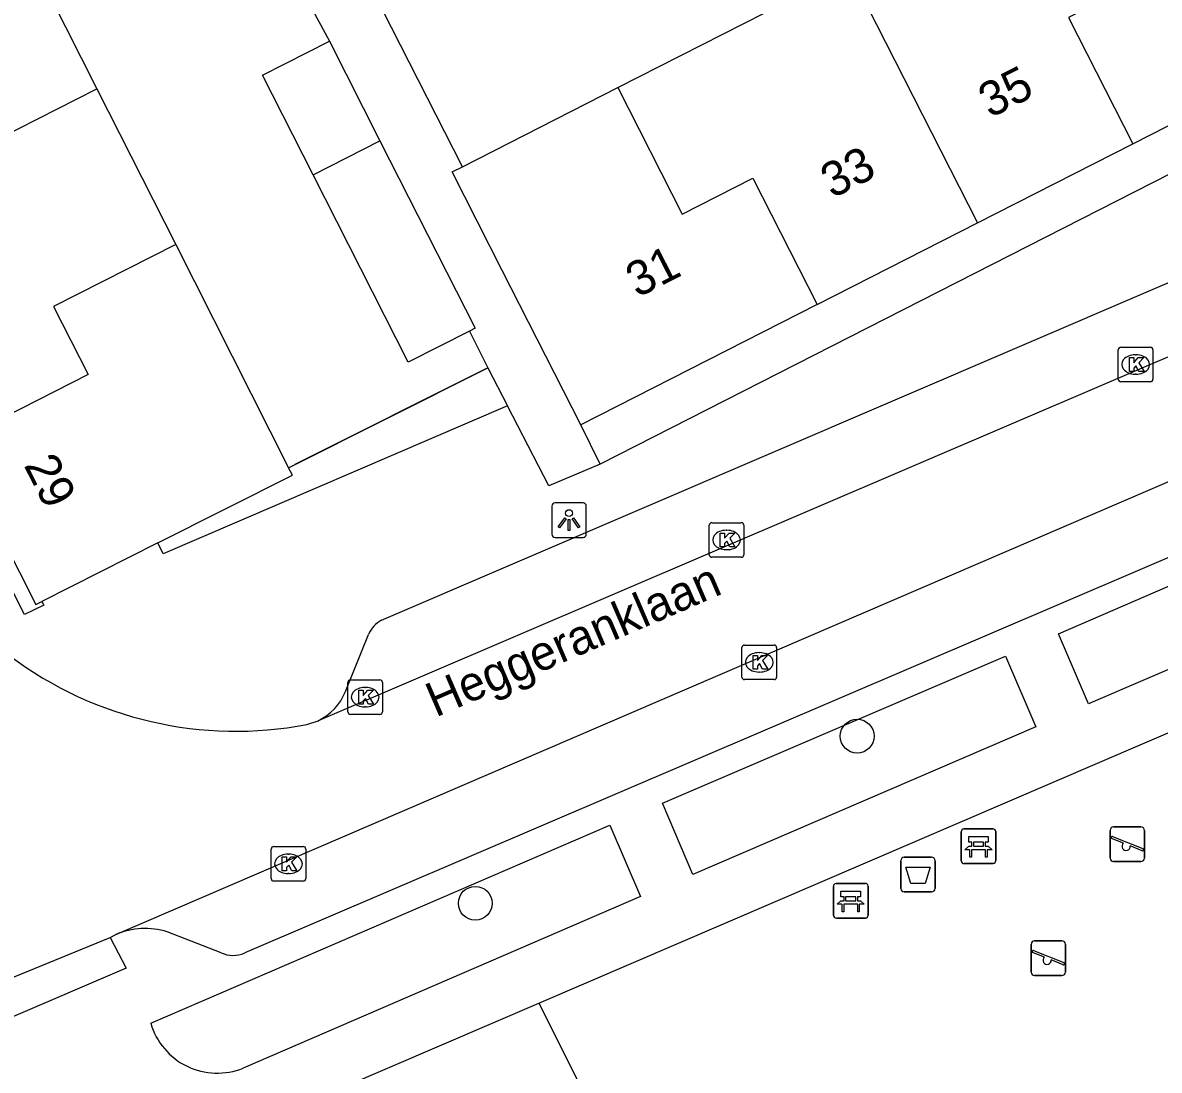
# Model space of a CAD drawing. Extents: x 162347 to 162868, y 381221 to 381813.
# Drawn here: x 162493.3 to 162526.14, y 381520.05 to 381550.31 of the extents above; entities that cross this region are included whole.
import ezdxf

# ---------------------------------------------------------------- set-up
doc = ezdxf.new("R2010")
doc.units = 0
for name, color, linetype in [('IMGEO_Afvalbak', 7, 'Continuous'), ('IMGEO_Bank', 7, 'Continuous'), ('IMGEO_Boom', 7, 'Continuous'), ('IMGEO_Groenvoorziening', 7, 'Continuous'), ('IMGEO_Kolk', 7, 'Continuous'), ('IMGEO_Lichtpunt', 7, 'Continuous'), ('IMGEO_Muur', 7, 'Continuous'), ('IMGEO_Openbare_ruimte_label', 7, 'Continuous'), ('IMGEO_Pand', 7, 'Continuous'), ('IMGEO_Pand_nummerreeks', 7, 'Continuous'), ('IMGEO_Rijbaan_lokaal_open', 7, 'Continuous'), ('IMGEO_Speelvoorziening', 7, 'Continuous'), ('IMGEO_Terreindeel_onvherhard', 7, 'Continuous'), ('IMGEO_Voetpad_open', 7, 'Continuous')]:
    doc.layers.add(name, color=color, linetype=linetype)

msp = doc.modelspace()

# ---------------------------------------------------------------- linework, layer by layer
at = {"layer": 'IMGEO_Afvalbak'}
for p, q in [((162518.676, 381525.301), (162518.676, 381526.101)), ((162518.676, 381526.101), (162518.676, 381525.301)), ((162518.776, 381526.201), (162519.566, 381526.201)), ((162519.566, 381526.201), (162518.776, 381526.201)), ((162519.666, 381526.101), (162519.666, 381525.301)), ((162519.666, 381525.301), (162519.666, 381526.101)), ((162519.566, 381525.201), (162518.776, 381525.201)), ((162518.776, 381525.201), (162519.566, 381525.201))]:
    msp.add_line(p, q, dxfattribs=at)
msp.add_lwpolyline([(162518.819, 381525.915), (162519.523, 381525.915), (162519.374, 381525.445), (162518.968, 381525.445), (162518.819, 381525.915)], dxfattribs=at)
for centre, start, end in [((162518.776, 381526.101), 90, 180), ((162518.776, 381526.101), 90, 180), ((162519.566, 381526.101), 0, 90), ((162519.566, 381526.101), 360, 90), ((162518.776, 381525.301), 180, 270), ((162518.776, 381525.301), 180, 270), ((162519.566, 381525.301), 270, 0), ((162519.566, 381525.301), 270, 0)]:
    msp.add_arc(centre, 0.1, start, end, dxfattribs=at)
at = {"layer": 'IMGEO_Bank'}
for p, q in [((162520.42, 381526.095), (162520.42, 381526.936)), ((162520.42, 381526.936), (162520.42, 381526.095)), ((162520.495, 381527.02), (162521.336, 381527.02)), ((162521.336, 381527.02), (162520.495, 381527.02)), ((162521.42, 381526.945), (162521.42, 381526.104)), ((162521.42, 381526.104), (162521.42, 381526.945)), ((162520.729, 381526.526), (162520.729, 381526.632)), ((162520.773, 381526.632), (162520.773, 381526.526)), ((162521.061, 381526.638), (162520.779, 381526.638)), ((162521.067, 381526.526), (162521.067, 381526.632)), ((162521.111, 381526.632), (162521.111, 381526.526)), ((162521.117, 381526.418), (162520.724, 381526.418)), ((162520.779, 381526.52), (162521.061, 381526.52)), ((162521.345, 381526.02), (162520.504, 381526.02)), ((162520.504, 381526.02), (162521.345, 381526.02)), ((162516.728, 381524.518), (162516.728, 381525.359)), ((162516.728, 381525.359), (162516.728, 381524.518)), ((162516.803, 381525.443), (162517.644, 381525.443)), ((162517.644, 381525.443), (162516.803, 381525.443)), ((162517.728, 381525.368), (162517.728, 381524.527)), ((162517.728, 381524.527), (162517.728, 381525.368)), ((162517.037, 381524.949), (162517.037, 381525.055)), ((162517.081, 381525.055), (162517.081, 381524.949)), ((162517.369, 381525.061), (162517.087, 381525.061)), ((162517.087, 381524.943), (162517.369, 381524.943)), ((162517.375, 381524.949), (162517.375, 381525.055)), ((162517.419, 381525.055), (162517.419, 381524.949)), ((162517.425, 381524.841), (162517.032, 381524.841)), ((162517.653, 381524.443), (162516.812, 381524.443)), ((162516.812, 381524.443), (162517.653, 381524.443))]:
    msp.add_line(p, q, dxfattribs=at)
for points in [[(162520.723, 381526.638), (162520.637, 381526.638), (162520.637, 381526.799), (162521.2, 381526.799), (162521.2, 381526.638), (162521.117, 381526.638)], [(162520.667, 381526.418), (162520.525, 381526.418), (162520.637, 381526.52), (162520.723, 381526.52)], [(162520.717, 381526.411), (162520.717, 381526.204), (162520.674, 381526.204), (162520.674, 381526.411)], [(162521.117, 381526.52), (162521.2, 381526.52), (162521.312, 381526.418), (162521.173, 381526.418)], [(162521.167, 381526.411), (162521.167, 381526.204), (162521.123, 381526.204), (162521.123, 381526.411)], [(162516.975, 381524.841), (162516.833, 381524.841), (162516.945, 381524.943), (162517.031, 381524.943)], [(162517.031, 381525.061), (162516.945, 381525.061), (162516.945, 381525.222), (162517.508, 381525.222), (162517.508, 381525.061), (162517.425, 381525.061)], [(162517.425, 381524.943), (162517.508, 381524.943), (162517.62, 381524.841), (162517.481, 381524.841)], [(162517.025, 381524.834), (162517.025, 381524.627), (162516.982, 381524.627), (162516.982, 381524.834)], [(162517.475, 381524.834), (162517.475, 381524.627), (162517.431, 381524.627), (162517.431, 381524.834)]]:
    msp.add_lwpolyline(points, dxfattribs=at)
for centre, radius, start, end in [((162520.498, 381526.942), 0.0779, 92.4484, 184.2845), ((162520.498, 381526.942), 0.0779, 92.4484, 184.2845), ((162521.342, 381526.942), 0.0779, 2.4484, 94.2845), ((162521.342, 381526.942), 0.0779, 2.4484, 94.2845), ((162520.722, 381526.631), 0.00671, 2.8957, 87.1043), ((162520.779, 381526.631), 0.00671, 92.8957, 177.1043), ((162521.061, 381526.631), 0.00671, 2.8957, 87.1043), ((162521.118, 381526.631), 0.00671, 92.8957, 177.1043), ((162520.667, 381526.411), 0.00671, 2.8957, 87.1043), ((162520.724, 381526.411), 0.00671, 92.8957, 177.1043), ((162520.722, 381526.527), 0.00671, 272.8957, 357.1043), ((162520.779, 381526.527), 0.00671, 182.8957, 267.1043), ((162521.061, 381526.527), 0.00671, 272.8957, 357.1043), ((162521.118, 381526.527), 0.00671, 182.8957, 267.1043), ((162521.116, 381526.411), 0.00671, 2.8957, 87.1043), ((162521.173, 381526.411), 0.00671, 92.8957, 177.1043), ((162520.498, 381526.098), 0.0779, 182.4484, 274.2845), ((162520.498, 381526.098), 0.0779, 182.4484, 274.2845), ((162521.342, 381526.098), 0.0779, 272.4484, 4.2845), ((162521.342, 381526.098), 0.0779, 272.4484, 4.2845), ((162516.806, 381525.365), 0.0779, 92.4484, 184.2845), ((162516.806, 381525.365), 0.0779, 92.4484, 184.2845), ((162517.65, 381525.365), 0.0779, 2.4484, 94.2845), ((162517.65, 381525.365), 0.0779, 2.4484, 94.2845), ((162517.03, 381525.054), 0.00671, 2.8957, 87.1043), ((162517.03, 381524.95), 0.00671, 272.8957, 357.1043), ((162517.087, 381525.054), 0.00671, 92.8957, 177.1043), ((162517.087, 381524.95), 0.00671, 182.8957, 267.1043), ((162517.369, 381525.054), 0.00671, 2.8957, 87.1043), ((162517.369, 381524.95), 0.00671, 272.8957, 357.1043), ((162517.426, 381525.054), 0.00671, 92.8957, 177.1043), ((162517.426, 381524.95), 0.00671, 182.8957, 267.1043), ((162516.975, 381524.834), 0.00671, 2.8957, 87.1043), ((162517.032, 381524.834), 0.00671, 92.8957, 177.1043), ((162517.424, 381524.834), 0.00671, 2.8957, 87.1043), ((162517.481, 381524.834), 0.00671, 92.8957, 177.1043), ((162516.806, 381524.521), 0.0779, 182.4484, 274.2845), ((162516.806, 381524.521), 0.0779, 182.4484, 274.2845), ((162517.65, 381524.521), 0.0779, 272.4484, 4.2845), ((162517.65, 381524.521), 0.0779, 272.4484, 4.2845)]:
    msp.add_arc(centre, radius, start, end, dxfattribs=at)
at = {"layer": 'IMGEO_Boom'}
for centre in [(162517.413, 381529.699), (162506.378, 381524.87)]:
    msp.add_circle(centre, 0.489, dxfattribs=at)
at = {"layer": 'IMGEO_Groenvoorziening'}
msp.add_lwpolyline([(162508.217, 381521.986), (162509, 381520.416), (162514.4, 381509.584)], dxfattribs=at)
at = {"layer": 'IMGEO_Kolk'}
for p, q in [((162524.96, 381540.012), (162524.96, 381540.864)), ((162525.035, 381540.938), (162525.887, 381540.938)), ((162525.448, 381540.718), (162525.473, 381540.718)), ((162525.961, 381540.864), (162525.961, 381540.012)), ((162525.471, 381540.158), (162525.446, 381540.158)), ((162525.887, 381539.938), (162525.035, 381539.938)), ((162513.138, 381534.941), (162513.138, 381535.793)), ((162513.213, 381535.867), (162514.065, 381535.867)), ((162514.139, 381535.793), (162514.139, 381534.941)), ((162513.626, 381535.647), (162513.651, 381535.647)), ((162514.065, 381534.867), (162513.213, 381534.867)), ((162513.649, 381535.087), (162513.624, 381535.087)), ((162514.085, 381531.406), (162514.085, 381532.258)), ((162514.16, 381532.332), (162515.012, 381532.332)), ((162515.086, 381532.258), (162515.086, 381531.406)), ((162514.573, 381532.112), (162514.598, 381532.112)), ((162514.596, 381531.552), (162514.571, 381531.552)), ((162502.695, 381530.401), (162502.695, 381531.253)), ((162502.77, 381531.327), (162503.622, 381531.327)), ((162503.696, 381531.253), (162503.696, 381530.401)), ((162515.012, 381531.332), (162514.16, 381531.332)), ((162503.183, 381531.107), (162503.208, 381531.107)), ((162503.206, 381530.547), (162503.181, 381530.547)), ((162503.622, 381530.327), (162502.77, 381530.327)), ((162500.479, 381525.583), (162500.479, 381526.435)), ((162500.554, 381526.509), (162501.406, 381526.509)), ((162500.967, 381526.289), (162500.992, 381526.289)), ((162501.48, 381526.435), (162501.48, 381525.583)), ((162500.99, 381525.729), (162500.965, 381525.729)), ((162501.406, 381525.509), (162500.554, 381525.509))]:
    msp.add_line(p, q, dxfattribs=at)
for points in [[(162524.96, 381540.012), (162524.96, 381540.864)], [(162525.035, 381540.938), (162525.887, 381540.938)], [(162525.961, 381540.864), (162525.961, 381540.012)], [(162525.281, 381540.638), (162525.404, 381540.638), (162525.404, 381540.487), (162525.534, 381540.638), (162525.698, 381540.638), (162525.552, 381540.487), (162525.705, 381540.238), (162525.553, 381540.238), (162525.468, 381540.402), (162525.404, 381540.335), (162525.404, 381540.238), (162525.281, 381540.238), (162525.281, 381540.638)], [(162525.887, 381539.938), (162525.035, 381539.938)], [(162513.138, 381534.941), (162513.138, 381535.793)], [(162513.213, 381535.867), (162514.065, 381535.867)], [(162514.139, 381535.793), (162514.139, 381534.941)], [(162513.459, 381535.567), (162513.582, 381535.567), (162513.582, 381535.416), (162513.712, 381535.567), (162513.876, 381535.567), (162513.73, 381535.416), (162513.883, 381535.167), (162513.731, 381535.167), (162513.646, 381535.331), (162513.582, 381535.264), (162513.582, 381535.167), (162513.459, 381535.167), (162513.459, 381535.567)], [(162514.065, 381534.867), (162513.213, 381534.867)], [(162514.085, 381531.406), (162514.085, 381532.258)], [(162514.16, 381532.332), (162515.012, 381532.332)], [(162515.086, 381532.258), (162515.086, 381531.406)], [(162514.406, 381532.032), (162514.529, 381532.032), (162514.529, 381531.881), (162514.659, 381532.032), (162514.823, 381532.032), (162514.677, 381531.881), (162514.83, 381531.632), (162514.678, 381531.632), (162514.593, 381531.796), (162514.529, 381531.729), (162514.529, 381531.632), (162514.406, 381531.632), (162514.406, 381532.032)], [(162502.695, 381530.401), (162502.695, 381531.253)], [(162502.77, 381531.327), (162503.622, 381531.327)], [(162503.696, 381531.253), (162503.696, 381530.401)], [(162515.012, 381531.332), (162514.16, 381531.332)], [(162503.016, 381531.027), (162503.139, 381531.027), (162503.139, 381530.876), (162503.269, 381531.027), (162503.433, 381531.027), (162503.287, 381530.876), (162503.44, 381530.627), (162503.288, 381530.627), (162503.203, 381530.791), (162503.139, 381530.724), (162503.139, 381530.627), (162503.016, 381530.627), (162503.016, 381531.027)], [(162503.622, 381530.327), (162502.77, 381530.327)], [(162500.479, 381525.583), (162500.479, 381526.435)], [(162500.554, 381526.509), (162501.406, 381526.509)], [(162501.48, 381526.435), (162501.48, 381525.583)], [(162500.8, 381526.209), (162500.923, 381526.209), (162500.923, 381526.058), (162501.053, 381526.209), (162501.217, 381526.209), (162501.071, 381526.058), (162501.224, 381525.809), (162501.072, 381525.809), (162500.987, 381525.973), (162500.923, 381525.906), (162500.923, 381525.809), (162500.8, 381525.809), (162500.8, 381526.209)], [(162501.406, 381525.509), (162500.554, 381525.509)]]:
    msp.add_lwpolyline(points, dxfattribs=at)
for centre, start, end in [((162525.037, 381540.862), 91.552, 178.448), ((162525.037, 381540.862), 91.552, 178.448), ((162525.885, 381540.862), 1.552, 88.448), ((162525.885, 381540.862), 1.552, 88.448), ((162525.037, 381540.014), 181.552, 268.448), ((162525.037, 381540.014), 181.552, 268.448), ((162525.885, 381540.014), 271.552, 358.448), ((162525.885, 381540.014), 271.552, 358.448), ((162513.215, 381535.791), 91.552, 178.448), ((162513.215, 381535.791), 91.552, 178.448), ((162514.063, 381535.791), 1.552, 88.448), ((162514.063, 381535.791), 1.552, 88.448), ((162513.215, 381534.943), 181.552, 268.448), ((162513.215, 381534.943), 181.552, 268.448), ((162514.063, 381534.943), 271.552, 358.448), ((162514.063, 381534.943), 271.552, 358.448), ((162514.162, 381532.256), 91.552, 178.448), ((162514.162, 381532.256), 91.552, 178.448), ((162515.01, 381532.256), 1.552, 88.448), ((162515.01, 381532.256), 1.552, 88.448), ((162502.772, 381531.251), 91.552, 178.448), ((162502.772, 381531.251), 91.552, 178.448), ((162503.62, 381531.251), 1.552, 88.448), ((162503.62, 381531.251), 1.552, 88.448), ((162514.162, 381531.408), 181.552, 268.448), ((162514.162, 381531.408), 181.552, 268.448), ((162515.01, 381531.408), 271.552, 358.448), ((162515.01, 381531.408), 271.552, 358.448), ((162502.772, 381530.403), 181.552, 268.448), ((162502.772, 381530.403), 181.552, 268.448), ((162503.62, 381530.403), 271.552, 358.448), ((162503.62, 381530.403), 271.552, 358.448), ((162500.556, 381526.433), 91.552, 178.448), ((162500.556, 381526.433), 91.552, 178.448), ((162501.404, 381526.433), 1.552, 88.448), ((162501.404, 381526.433), 1.552, 88.448), ((162500.556, 381525.585), 181.552, 268.448), ((162500.556, 381525.585), 181.552, 268.448), ((162501.404, 381525.585), 271.552, 358.448), ((162501.404, 381525.585), 271.552, 358.448)]:
    msp.add_arc(centre, 0.0765, start, end, dxfattribs=at)
for centre, major_axis, ratio, start_param, end_param in [((162525.447, 381540.438), (-0.387, 0.002), 0.722429, 4.712389, 7.853982), ((162525.472, 381540.438), (-0.39, 0.002), 0.717154, 1.570796, 4.712389), ((162513.625, 381535.367), (-0.387, 0.002), 0.722429, 4.712389, 7.853982), ((162513.65, 381535.367), (-0.39, 0.002), 0.717154, 1.570796, 4.712389), ((162514.572, 381531.832), (-0.387, 0.002), 0.722429, 4.712389, 7.853982), ((162514.597, 381531.832), (-0.39, 0.002), 0.717154, 1.570796, 4.712389), ((162503.182, 381530.827), (-0.387, 0.002), 0.722429, 4.712389, 7.853982), ((162503.207, 381530.827), (-0.39, 0.002), 0.717154, 1.570796, 4.712389), ((162500.966, 381526.009), (-0.387, 0.002), 0.722429, 4.712389, 7.853982), ((162500.991, 381526.009), (-0.39, 0.002), 0.717154, 1.570796, 4.712389)]:
    msp.add_ellipse(centre, major_axis=major_axis, ratio=ratio, start_param=start_param, end_param=end_param, dxfattribs=at)
at = {"layer": 'IMGEO_Lichtpunt'}
for p, q in [((162509.491, 381536.439), (162508.683, 381536.439)), ((162509.491, 381536.439), (162508.683, 381536.439)), ((162508.589, 381536.344), (162508.589, 381535.537)), ((162508.589, 381536.344), (162508.589, 381535.537)), ((162509.585, 381535.537), (162509.585, 381536.344)), ((162509.585, 381535.537), (162509.585, 381536.344)), ((162508.683, 381535.443), (162509.491, 381535.443)), ((162508.683, 381535.443), (162509.491, 381535.443))]:
    msp.add_line(p, q, dxfattribs=at)
for points in [[(162508.963, 381536.008), (162509.002, 381535.98), (162508.814, 381535.718), (162508.776, 381535.745), (162508.963, 381536.008)], [(162509.065, 381535.96), (162509.112, 381535.96), (162509.112, 381535.638), (162509.065, 381535.638), (162509.065, 381535.96)], [(162509.175, 381535.98), (162509.213, 381536.007), (162509.4, 381535.745), (162509.361, 381535.717), (162509.175, 381535.98)]]:
    msp.add_lwpolyline(points, dxfattribs=at)
msp.add_circle((162509.088, 381536.142), 0.0994, dxfattribs=at)
for centre, start, end in [((162508.683, 381536.344), 90, 180), ((162508.683, 381536.344), 90, 180), ((162509.491, 381536.344), 0, 90), ((162509.491, 381536.344), 0, 90), ((162508.683, 381535.537), 180, 270), ((162508.683, 381535.537), 180, 270), ((162509.491, 381535.537), 270, 0), ((162509.491, 381535.537), 270, 360)]:
    msp.add_arc(centre, 0.0946, start, end, dxfattribs=at)
at = {"layer": 'IMGEO_Muur'}
msp.add_lwpolyline([(162506.739, 381540.345), (162501.168, 381537.547)], dxfattribs=at)
at = {"layer": 'IMGEO_Pand'}
for points in [[(162523.625, 381555.117), (162525.484, 381551.465), (162523.52, 381550.466), (162525.378, 381546.813)], [(162493.17, 381552.905), (162495.445, 381548.407)], [(162510.497, 381548.437), (162517.175, 381551.836)], [(162517.175, 381551.836), (162520.892, 381544.53)], [(162525.378, 381546.813), (162532.073, 381550.22)], [(162501.689, 381545.918), (162500.228, 381548.796), (162502.162, 381549.778)], [(162502.162, 381549.778), (162503.623, 381546.9)], [(162488.041, 381544.647), (162495.445, 381548.407)], [(162495.445, 381548.407), (162497.722, 381543.904)], [(162506.006, 381546.152), (162510.497, 381548.437)], [(162510.497, 381548.437), (162512.355, 381544.785), (162514.399, 381545.825), (162516.259, 381542.172)], [(162501.689, 381545.918), (162503.623, 381546.9)], [(162503.623, 381546.9), (162506.372, 381541.485), (162506.208, 381541.402)], [(162520.892, 381544.53), (162525.378, 381546.813)], [(162509.427, 381538.695), (162507.159, 381543.152), (162505.709, 381546.001), (162506.006, 381546.152)], [(162506.208, 381541.402), (162504.438, 381540.503), (162501.689, 381545.918)], [(162516.259, 381542.172), (162520.892, 381544.53)], [(162497.722, 381543.904), (162494.191, 381542.111), (162495.188, 381540.147), (162491.312, 381538.178)], [(162497.722, 381543.904), (162500.984, 381537.454)], [(162516.259, 381542.172), (162509.427, 381538.695)], [(162491.312, 381538.178), (162493.677, 381533.501), (162493.857, 381533.592)], [(162497.202, 381535.283), (162501.094, 381537.236), (162500.984, 381537.454)], [(162497.202, 381535.283), (162493.857, 381533.592)]]:
    msp.add_lwpolyline(points, dxfattribs=at)
at = {"layer": 'IMGEO_Rijbaan_lokaal_open'}
for points in [[(162533.181, 381543.553), (162501.836, 381530.146)], [(162495.993, 381523.971), (162534.166, 381540.393)], [(162501.509, 381530.036), (162501.836, 381530.146)], [(162495.827, 381523.884), (162495.993, 381523.971)], [(162492.43, 381522.496), (162492.451, 381522.505), (162495.827, 381523.884)]]:
    msp.add_lwpolyline(points, dxfattribs=at)
msp.add_arc((162499.46, 381540.729), 10.888, 233.1735, 280.848, dxfattribs=at)
at = {"layer": 'IMGEO_Speelvoorziening'}
for p, q in [((162524.724, 381526.177), (162524.724, 381526.977)), ((162524.724, 381526.977), (162524.724, 381526.177)), ((162524.824, 381527.077), (162525.614, 381527.077)), ((162525.614, 381527.077), (162524.824, 381527.077)), ((162525.714, 381526.977), (162525.714, 381526.177)), ((162525.714, 381526.177), (162525.714, 381526.977)), ((162525.107, 381526.605), (162524.768, 381526.742)), ((162524.793, 381526.802), (162525.669, 381526.449)), ((162525.645, 381526.389), (162525.305, 381526.526)), ((162525.614, 381526.077), (162524.824, 381526.077)), ((162524.824, 381526.077), (162525.614, 381526.077)), ((162522.441, 381522.884), (162522.441, 381523.684)), ((162522.441, 381523.684), (162522.441, 381522.884)), ((162522.541, 381523.784), (162523.331, 381523.784)), ((162523.331, 381523.784), (162522.541, 381523.784)), ((162523.431, 381523.684), (162523.431, 381522.884)), ((162523.431, 381522.884), (162523.431, 381523.684)), ((162522.824, 381523.312), (162522.485, 381523.449)), ((162522.51, 381523.509), (162523.386, 381523.156)), ((162523.362, 381523.096), (162523.022, 381523.233)), ((162523.331, 381522.784), (162522.541, 381522.784)), ((162522.541, 381522.784), (162523.331, 381522.784))]:
    msp.add_line(p, q, dxfattribs=at)
for centre, radius, start, end in [((162524.824, 381526.977), 0.1, 90, 180), ((162524.824, 381526.977), 0.1, 90, 180), ((162525.614, 381526.977), 0.1, 0, 90), ((162525.614, 381526.977), 0.1, 360, 90), ((162524.781, 381526.772), 0.0327, 68.078, 248.078), ((162525.186, 381526.515), 0.12, 130.9928, 5.1632), ((162525.657, 381526.419), 0.0327, 248.078, 68.078), ((162524.824, 381526.177), 0.1, 180, 270), ((162524.824, 381526.177), 0.1, 180, 270), ((162525.614, 381526.177), 0.1, 270, 0), ((162525.614, 381526.177), 0.1, 270, 0), ((162522.541, 381523.684), 0.1, 90, 180), ((162522.541, 381523.684), 0.1, 90, 180), ((162523.331, 381523.684), 0.1, 0, 90), ((162523.331, 381523.684), 0.1, 360, 90), ((162522.498, 381523.479), 0.0327, 68.078, 248.078), ((162522.903, 381523.222), 0.12, 130.9928, 5.1632), ((162523.374, 381523.126), 0.0327, 248.078, 68.078), ((162522.541, 381522.884), 0.1, 180, 270), ((162522.541, 381522.884), 0.1, 180, 270), ((162523.331, 381522.884), 0.1, 270, 0), ((162523.331, 381522.884), 0.1, 270, 0)]:
    msp.add_arc(centre, radius, start, end, dxfattribs=at)
at = {"layer": 'IMGEO_Terreindeel_onvherhard'}
msp.add_lwpolyline([(162500.984, 381537.454), (162506.739, 381540.345)], dxfattribs=at)
at = {"layer": 'IMGEO_Voetpad_open'}
for points in [[(162493.857, 381533.592), (162493.913, 381533.481), (162493.347, 381533.215), (162453.435, 381611.809), (162453.968, 381612.034)], [(162499.827, 381554.108), (162502.162, 381549.778)], [(162506.006, 381546.152), (162503.446, 381551.184)], [(162532.638, 381549.091), (162509.986, 381537.559)], [(162503.672, 381533.049), (162529.63, 381544.187)], [(162506.208, 381541.402), (162506.739, 381540.345)], [(162506.739, 381540.345), (162507.307, 381539.243)], [(162507.307, 381539.243), (162497.363, 381534.965), (162497.202, 381535.283)], [(162509.986, 381537.559), (162508.501, 381536.927), (162507.307, 381539.243)], [(162537.402, 381536.341), (162524.096, 381530.629), (162523.23, 381532.652), (162538.381, 381539.216)], [(162509.986, 381537.559), (162509.427, 381538.695)], [(162531.993, 381537.251), (162499.714, 381523.434)], [(162502.626, 381530.986), (162503.293, 381532.637)], [(162508.217, 381521.986), (162531.132, 381531.827)], [(162521.7, 381532.007), (162522.572, 381529.968), (162512.662, 381525.701), (162511.787, 381527.762), (162521.7, 381532.007)], [(162496.999, 381521.404), (162510.27, 381527.123)], [(162510.27, 381527.123), (162511.154, 381525.065), (162499.674, 381520.107)], [(162499.037, 381523.438), (162497.475, 381524.049)], [(162495.827, 381523.884), (162496.291, 381522.996), (162492.902, 381521.543), (162492.43, 381522.496)], [(162491.115, 381514.642), (162508.217, 381521.986)]]:
    msp.add_lwpolyline(points, dxfattribs=at)
for centre, radius, start, end in [((162504.075, 381532.298), 0.852, 118.2146, 156.5633), ((162501.183, 381531.551), 1.549, 294.9097, 338.6043), ((162496.844, 381521.926), 2.215, 73.4407, 112.5849), ((162499.38, 381524.207), 0.842, 245.965, 293.358), ((162498.924, 381521.968), 2.006, 196.3213, 291.945)]:
    msp.add_arc(centre, radius, start, end, dxfattribs=at)

# ---------------------------------------------------------------- texts
at = {"layer": 'IMGEO_Openbare_ruimte_label'}
msp.add_text('Heggeranklaan', height=1, rotation=23.334, dxfattribs=at).set_placement((162505.233, 381530.234))
at = {"layer": 'IMGEO_Pand_nummerreeks'}
for s, rotation, p in [('35', 26.9725, (162521.256, 381547.543)), ('33', 26.9724, (162516.696, 381545.222)), ('31', 26.9749, (162511.064, 381542.355)), ('29', 296.8199, (162493.321, 381537.529))]:
    msp.add_text(s, height=1, rotation=rotation, dxfattribs=at).set_placement(p)

doc.saveas('drawing.dxf')
